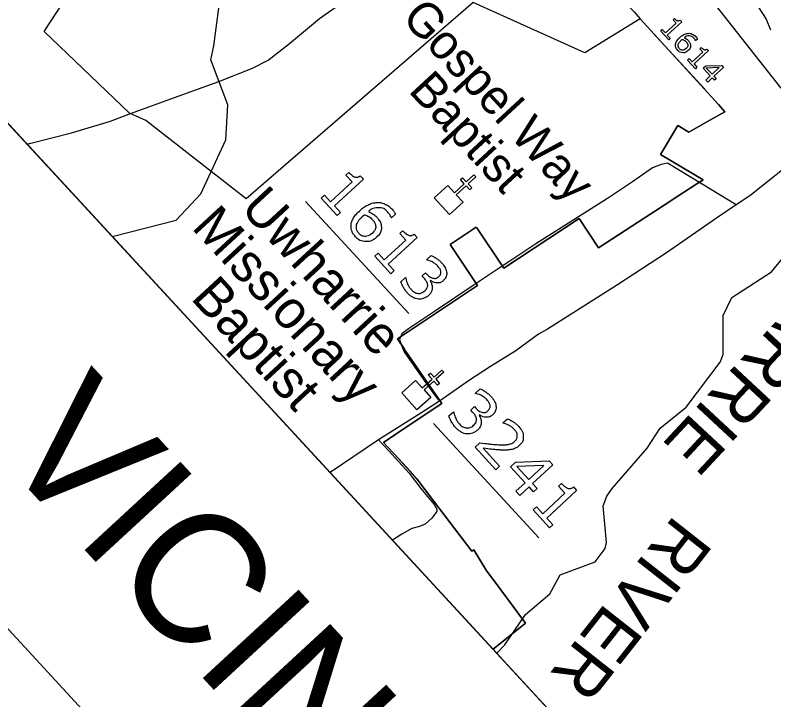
# Model space of a CAD drawing. Extents: x 1695041 to 1706254, y 786537 to 798223.
# Drawn here: x 1702759.1 to 1702961, y 796754.5 to 796936.6 of the extents above; entities that cross this region are included whole.
import ezdxf

# ---------------------------------------------------------------- set-up
doc = ezdxf.new("R2010")
doc.units = 0
for name, color, linetype in [('Default', 7, 'Continuous'), ('Old_Level_2', 7, 'Continuous'), ('Old_Level_30', 7, 'Continuous'), ('Old_Level_32', 7, 'Continuous')]:
    doc.layers.add(name, color=color, linetype=linetype)

msp = doc.modelspace()

# ---------------------------------------------------------------- linework, layer by layer
at = {"layer": 'Default'}
for p, q in [((1702636.99, 797037.98), (1703265.12, 796357.5)), ((1702683.46, 796987.65), (1702886.28, 796767.92)), ((1702683.46, 796987.65), (1702886.28, 796767.92)), ((1702569.98, 796976.12), (1703198.1, 796295.64)), ((1702928.77, 796931.9), (1702942.59, 796916.93)), ((1702836.31, 796887.01), (1702863.82, 796857.2)), ((1702870.38, 796828.01), (1702898.46, 796797.59)), ((1702859.9, 796819.89), (1702865.99, 796813.24)), ((1702859.9, 796819.89), (1702865.99, 796813.24)), ((1702886.28, 796767.92), (1702888.97, 796765))]:
    msp.add_line(p, q, dxfattribs=at)
for points in [[(1703207.65, 797564.73), (1702636.99, 797037.98), (1703265.12, 796357.5), (1703835.77, 796884.26)], [(1702925.41, 796935.68), (1702910.71, 796926.62), (1702880.93, 796939.99), (1702820.56, 796887.72), (1702793.87, 796908.61), (1702789.51, 796910.51), (1702766.84, 796932.24), (1702771.83, 796939.94), (1702770.51, 796956.02), (1702774.36, 796959.43), (1702767.63, 796967.11), (1702772.81, 796971.72), (1702783.62, 796979.72), (1702783.43, 796981.21), (1702797.1, 796993.15), (1702779.26, 797011.19), (1702762.34, 797007.42), (1702760.1, 797010.1), (1702716.96, 796974.07), (1702714.33, 796993.89), (1702694.56, 796987.03), (1702684.89, 796991.85), (1702683.46, 796987.65)], [(1702925.41, 796935.68), (1702910.71, 796926.62), (1702880.93, 796939.99), (1702820.56, 796887.72), (1702793.87, 796908.61), (1702789.51, 796910.51), (1702766.84, 796932.24), (1702771.83, 796939.94), (1702770.51, 796956.02), (1702774.36, 796959.43), (1702767.63, 796967.11), (1702772.81, 796971.72), (1702783.62, 796979.72), (1702783.43, 796981.21), (1702797.1, 796993.15), (1702779.26, 797011.19), (1702762.34, 797007.42), (1702760.1, 797010.1), (1702716.96, 796974.07), (1702714.33, 796993.89), (1702694.56, 796987.03), (1702684.89, 796991.85), (1702683.46, 796987.65)], [(1702969.78, 796940.73), (1702969.33, 796939.28), (1702965.99, 796925.42), (1702964.15, 796917.75), (1702962.89, 796917.17), (1702932.55, 796955.73), (1702924.73, 796965.57), (1702922.88, 796967.64), (1702932.74, 796975.84), (1702936, 796978.21), (1702924.89, 796991.85), (1702917.84, 796986.09), (1702911.88, 796981.22), (1702914.79, 796977.7), (1702908.54, 796972.43), (1702903.8, 796968.42), (1702898.61, 796964.04), (1702901.91, 796960.89), (1702912.63, 796949.21), (1702923.77, 796937.5), (1702925.41, 796935.68)], [(1702969.78, 796940.73), (1702969.33, 796939.28), (1702965.99, 796925.42), (1702964.15, 796917.75), (1702962.89, 796917.17), (1702932.55, 796955.73), (1702924.73, 796965.57), (1702922.88, 796967.64), (1702932.74, 796975.84), (1702936, 796978.21), (1702924.89, 796991.85), (1702917.84, 796986.09), (1702911.88, 796981.22), (1702914.79, 796977.7), (1702908.54, 796972.43), (1702903.8, 796968.42), (1702898.61, 796964.04), (1702901.91, 796960.89), (1702912.63, 796949.21), (1702923.77, 796937.5), (1702925.41, 796935.68)], [(1702929.65, 796971.07), (1702932.14, 796967.77), (1702939.12, 796959.62), (1702945.77, 796951.98), (1702950, 796947.1), (1702951.94, 796944.71), (1702954.16, 796942.3), (1702956.83, 796938.82), (1702958.88, 796935.58), (1702960.04, 796932.69)], [(1702811.13, 796924.7), (1702811.93, 796928.47), (1702813.39, 796939.15), (1702814.28, 796944.71)], [(1702930.77, 796899.57), (1702935.39, 796907.26), (1702938.35, 796905.48), (1702945.38, 796909.47), (1702945.54, 796909.57), (1702947.96, 796910.93), (1702946.25, 796912.81), (1702925.41, 796935.68)], [(1702930.77, 796899.57), (1702935.39, 796907.26), (1702938.35, 796905.48), (1702945.38, 796909.47), (1702945.54, 796909.57), (1702947.96, 796910.93), (1702946.25, 796912.81), (1702925.41, 796935.68)], [(1702925.41, 796935.68), (1702946.25, 796912.81), (1702947.96, 796910.93), (1702945.54, 796909.57), (1702945.38, 796909.47), (1702938.35, 796905.48), (1702935.39, 796907.26), (1702930.77, 796899.57)], [(1702925.41, 796935.68), (1702946.25, 796912.81), (1702947.96, 796910.93), (1702945.54, 796909.57), (1702945.38, 796909.47), (1702938.35, 796905.48), (1702935.39, 796907.26), (1702930.77, 796899.57)], [(1702932.98, 796930.06), (1702930.86, 796932.36), (1702931.29, 796932.76), (1702932.11, 796931.88), (1702934.95, 796934.5), (1702934.14, 796935.39), (1702934.53, 796935.74)], [(1702936.03, 796935.3), (1702936.44, 796934.86), (1702932.62, 796931.33), (1702933.41, 796930.46), (1702932.98, 796930.06)], [(1702940.69, 796930.26), (1702940.14, 796929.75), (1702940.12, 796929.78)], [(1702940.08, 796922.37), (1702937.96, 796924.67), (1702938.39, 796925.07), (1702939.21, 796924.19), (1702942.05, 796926.81), (1702941.24, 796927.69), (1702941.63, 796928.05)], [(1702943.13, 796927.61), (1702943.54, 796927.17), (1702939.72, 796923.64), (1702940.51, 796922.77), (1702940.08, 796922.37)], [(1702784.91, 796877.73), (1702801.89, 796882.09), (1702808.46, 796889.09), (1702815.17, 796903.46), (1702815.67, 796912.73), (1702811.13, 796924.7)], [(1702945.14, 796919.29), (1702944.56, 796919.92), (1702943.36, 796918.82), (1702942.86, 796919.36), (1702944.05, 796920.47), (1702942.18, 796922.5), (1702942.83, 796923.11), (1702947.12, 796923.26), (1702947.61, 796922.73), (1702945.02, 796920.34), (1702945.6, 796919.71), (1702945.14, 796919.29)], [(1702944.51, 796920.89), (1702946.43, 796922.66), (1702942.99, 796922.54), (1702944.51, 796920.89)], [(1702942.05, 796892.68), (1702942.19, 796892.77), (1702930.77, 796899.57)], [(1702942.05, 796892.68), (1702942.19, 796892.77), (1702930.77, 796899.57)], [(1702930.77, 796899.57), (1702942.19, 796892.77), (1702942.05, 796892.68)], [(1702930.77, 796899.57), (1702942.19, 796892.77), (1702942.05, 796892.68)], [(1702844.78, 796883.32), (1702840.52, 796887.94), (1702841.39, 796888.74), (1702843.03, 796886.97), (1702848.75, 796892.25), (1702847.11, 796894.03), (1702847.89, 796894.75)], [(1702850.92, 796893.86), (1702851.74, 796892.97), (1702844.05, 796885.86), (1702845.66, 796884.12), (1702844.78, 796883.32)], [(1702859.9, 796819.89), (1702858.28, 796821.64), (1702857.11, 796822.95), (1702864.45, 796827.87), (1702872.64, 796833.28), (1702862.9, 796847.39), (1702862.66, 796847.75), (1702860.8, 796850.5), (1702882.15, 796864.71), (1702874.8, 796875.62), (1702881.78, 796880.22), (1702881.96, 796880), (1702889.15, 796869.31), (1702909.2, 796882.51), (1702914.34, 796874.72), (1702933.54, 796887.23), (1702933.66, 796887.31), (1702940.51, 796891.73), (1702942.05, 796892.68)], [(1702859.9, 796819.89), (1702858.28, 796821.64), (1702857.11, 796822.95), (1702864.45, 796827.87), (1702872.64, 796833.28), (1702862.9, 796847.39), (1702862.66, 796847.75), (1702860.8, 796850.5), (1702882.15, 796864.71), (1702874.8, 796875.62), (1702881.78, 796880.22), (1702881.96, 796880), (1702889.15, 796869.31), (1702909.2, 796882.51), (1702914.34, 796874.72), (1702933.54, 796887.23), (1702933.66, 796887.31), (1702940.51, 796891.73), (1702942.05, 796892.68)], [(1702942.05, 796892.68), (1702940.51, 796891.73), (1702933.66, 796887.31), (1702933.54, 796887.23), (1702914.34, 796874.72), (1702909.2, 796882.51), (1702889.15, 796869.31), (1702881.96, 796880), (1702881.78, 796880.22), (1702874.8, 796875.62), (1702882.15, 796864.71), (1702860.8, 796850.5), (1702862.66, 796847.75), (1702862.9, 796847.39), (1702872.64, 796833.28), (1702864.45, 796827.87), (1702857.11, 796822.95), (1702858.28, 796821.64), (1702859.9, 796819.89)], [(1702942.05, 796892.68), (1702940.51, 796891.73), (1702933.66, 796887.31), (1702933.54, 796887.23), (1702914.34, 796874.72), (1702909.2, 796882.51), (1702889.15, 796869.31), (1702881.96, 796880), (1702881.78, 796880.22), (1702874.8, 796875.62), (1702882.15, 796864.71), (1702860.8, 796850.5), (1702862.66, 796847.75), (1702862.9, 796847.39), (1702872.64, 796833.28), (1702864.45, 796827.87), (1702857.11, 796822.95), (1702858.28, 796821.64), (1702859.9, 796819.89)], [(1702860.3, 796883.7), (1702859.2, 796882.68), (1702859.15, 796882.74)], [(1702859.08, 796867.83), (1702854.81, 796872.46), (1702855.68, 796873.26), (1702857.32, 796871.48), (1702863.05, 796876.77), (1702861.41, 796878.54), (1702862.19, 796879.27)], [(1702865.22, 796878.38), (1702866.04, 796877.49), (1702858.34, 796870.38), (1702859.95, 796868.64), (1702859.08, 796867.83)], [(1702868.63, 796871.5), (1702868.58, 796871.56), (1702869.77, 796872.67)], [(1702861.72, 796865.68), (1702862.92, 796866.79), (1702863, 796866.7)], [(1702867.83, 796866.71), (1702867.35, 796867.22), (1702868.3, 796868.1), (1702868.67, 796867.7)], [(1702869.59, 796865.98), (1702869.51, 796865.9)], [(1702881.62, 796835.98), (1702881.57, 796836.04), (1702882.81, 796837.19)], [(1702880.79, 796831.03), (1702880.3, 796831.56), (1702881.28, 796832.47), (1702881.66, 796832.05)], [(1702874.49, 796829.97), (1702875.72, 796831.11), (1702875.81, 796831.03)], [(1702882.61, 796830.28), (1702882.53, 796830.2)], [(1702888.94, 796828.06), (1702888.88, 796828.12), (1702890.13, 796829.26)], [(1702886.99, 796815.69), (1702881.47, 796821.67), (1702882.71, 796822.82)], [(1702865.99, 796813.24), (1702864.25, 796815.22), (1702859.9, 796819.89)], [(1702865.99, 796813.24), (1702864.25, 796815.22), (1702859.9, 796819.89)], [(1702883.62, 796821.39), (1702888.01, 796816.63), (1702886.99, 796815.69)], [(1702897.04, 796809.78), (1702895.83, 796811.1), (1702893.34, 796808.8), (1702892.29, 796809.94), (1702894.78, 796812.23), (1702890.88, 796816.46), (1702892.24, 796817.72), (1702901.16, 796818.04), (1702902.17, 796816.95), (1702896.78, 796811.97), (1702897.99, 796810.66), (1702897.04, 796809.78)], [(1702895.73, 796813.11), (1702899.72, 796816.79), (1702892.57, 796816.54), (1702895.73, 796813.11)], [(1702886.28, 796767.92), (1702894.9, 796774.87), (1702888.3, 796783.71), (1702884.4, 796788.94), (1702881.13, 796794.32), (1702880.63, 796794), (1702870.44, 796807.4), (1702865.99, 796813.24)], [(1702886.28, 796767.92), (1702894.9, 796774.87), (1702888.3, 796783.71), (1702884.4, 796788.94), (1702881.13, 796794.32), (1702880.63, 796794), (1702870.44, 796807.4), (1702865.99, 796813.24)], [(1702865.99, 796813.24), (1702870.44, 796807.4), (1702880.63, 796794), (1702881.13, 796794.32), (1702884.4, 796788.94), (1702888.3, 796783.71), (1702894.9, 796774.87), (1702886.28, 796767.92)], [(1702865.99, 796813.24), (1702870.44, 796807.4), (1702880.63, 796794), (1702881.13, 796794.32), (1702884.4, 796788.94), (1702888.3, 796783.71), (1702894.9, 796774.87), (1702886.28, 796767.92)], [(1702901.29, 796800.2), (1702896.88, 796804.97), (1702897.78, 796805.81), (1702899.47, 796803.97), (1702905.39, 796809.43), (1702903.69, 796811.27), (1702904.5, 796812.01)], [(1702907.63, 796811.09), (1702908.48, 796810.17), (1702900.52, 796802.83), (1702902.19, 796801.03), (1702901.29, 796800.2)]]:
    msp.add_lwpolyline(points, dxfattribs=at)
for points in [[(1702874.18, 796891.31), (1702875.97, 796889.38), (1702878.56, 796891.77), (1702877.55, 796892.85), (1702878.1, 796893.35), (1702879.1, 796892.27), (1702881.14, 796894.15), (1702881.64, 796893.61), (1702879.6, 796891.72), (1702880.6, 796890.64), (1702880.06, 796890.14), (1702879.06, 796891.22), (1702876.47, 796888.84), (1702878.28, 796886.87), (1702874.66, 796883.54), (1702870.57, 796887.97)], [(1702865.63, 796839.42), (1702867.39, 796837.47), (1702870.01, 796839.81), (1702869.02, 796840.91), (1702869.57, 796841.41), (1702870.56, 796840.31), (1702872.63, 796842.16), (1702873.12, 796841.61), (1702871.05, 796839.76), (1702872.04, 796838.66), (1702871.49, 796838.16), (1702870.5, 796839.26), (1702867.89, 796836.91), (1702869.66, 796834.93), (1702866, 796831.64), (1702861.97, 796836.13)]]:
    msp.add_lwpolyline(points, close=True, dxfattribs=at)
for points in [[(1702934.53, 796935.74), (1702934.69, 796935.56), (1702934.91, 796935.39), (1702935.13, 796935.21), (1702935.29, 796935.16), (1702935.48, 796935.09), (1702935.66, 796935.12), (1702935.84, 796935.14), (1702936.03, 796935.3)], [(1702938.19, 796927.18), (1702937.54, 796926.59), (1702936.74, 796926.63), (1702935.94, 796926.68), (1702935.37, 796927.3), (1702935.08, 796927.61), (1702934.94, 796927.96), (1702934.8, 796928.31), (1702934.81, 796928.68), (1702934.82, 796929.14), (1702935.08, 796929.64), (1702935.35, 796930.13), (1702935.9, 796930.64), (1702936.47, 796931.16), (1702937.02, 796931.44), (1702937.56, 796931.72), (1702938.15, 796931.77), (1702938.7, 796931.81), (1702939.25, 796931.59), (1702939.8, 796931.36), (1702940.28, 796930.83), (1702940.44, 796930.66), (1702940.53, 796930.53), (1702940.62, 796930.41), (1702940.69, 796930.26)], [(1702940.12, 796929.78), (1702940.09, 796929.9), (1702939.98, 796930.1), (1702939.87, 796930.29), (1702939.71, 796930.46), (1702939.15, 796931.07), (1702938.43, 796931.08), (1702937.71, 796931.09), (1702937, 796930.55), (1702937.37, 796930.45), (1702937.66, 796930.28), (1702937.95, 796930.12), (1702938.23, 796929.82), (1702938.48, 796929.55), (1702938.62, 796929.29), (1702938.76, 796929.04), (1702938.81, 796928.69), (1702938.86, 796928.28), (1702938.72, 796927.9), (1702938.57, 796927.53), (1702938.19, 796927.18)], [(1702937.63, 796927.74), (1702937.89, 796927.98), (1702938, 796928.22), (1702938.1, 796928.46), (1702938.06, 796928.76), (1702938.03, 796928.97), (1702937.91, 796929.16), (1702937.79, 796929.34), (1702937.63, 796929.52), (1702937.41, 796929.76), (1702937.16, 796929.91), (1702936.91, 796930.07), (1702936.59, 796930.18), (1702936.52, 796930.12), (1702936.46, 796930.07), (1702936.4, 796930.02), (1702936.31, 796929.94), (1702935.86, 796929.53), (1702935.69, 796929.19), (1702935.51, 796928.86), (1702935.51, 796928.56), (1702935.51, 796928.31), (1702935.59, 796928.11), (1702935.67, 796927.9), (1702935.84, 796927.72), (1702936.22, 796927.31), (1702936.69, 796927.31), (1702937.16, 796927.3), (1702937.63, 796927.74)], [(1702941.63, 796928.05), (1702941.79, 796927.87), (1702942.01, 796927.69), (1702942.23, 796927.52), (1702942.39, 796927.46), (1702942.58, 796927.4), (1702942.76, 796927.42), (1702942.94, 796927.45), (1702943.13, 796927.61)], [(1702847.89, 796894.75), (1702848.23, 796894.39), (1702848.67, 796894.03), (1702849.11, 796893.67), (1702849.42, 796893.57), (1702849.81, 796893.44), (1702850.17, 796893.49), (1702850.53, 796893.54), (1702850.92, 796893.86)], [(1702855.26, 796877.52), (1702853.96, 796876.31), (1702852.35, 796876.41), (1702850.73, 796876.51), (1702849.58, 796877.75), (1702849, 796878.38), (1702848.72, 796879.08), (1702848.44, 796879.78), (1702848.46, 796880.53), (1702848.48, 796881.46), (1702849.02, 796882.45), (1702849.56, 796883.45), (1702850.67, 796884.47), (1702851.8, 796885.52), (1702852.91, 796886.08), (1702854.01, 796886.65), (1702855.18, 796886.75), (1702856.3, 796886.84), (1702857.4, 796886.38), (1702858.5, 796885.92), (1702859.48, 796884.86), (1702859.79, 796884.52), (1702859.98, 796884.26), (1702860.16, 796884.01), (1702860.3, 796883.7)], [(1702859.15, 796882.74), (1702859.09, 796882.98), (1702858.87, 796883.38), (1702858.64, 796883.78), (1702858.33, 796884.11), (1702857.2, 796885.35), (1702855.75, 796885.37), (1702854.3, 796885.39), (1702852.87, 796884.3), (1702853.61, 796884.09), (1702854.19, 796883.76), (1702854.78, 796883.43), (1702855.34, 796882.82), (1702855.84, 796882.27), (1702856.13, 796881.77), (1702856.41, 796881.26), (1702856.51, 796880.54), (1702856.62, 796879.71), (1702856.33, 796878.97), (1702856.03, 796878.22), (1702855.26, 796877.52)], [(1702854.14, 796878.63), (1702854.67, 796879.13), (1702854.88, 796879.61), (1702855.08, 796880.09), (1702855, 796880.68), (1702854.94, 796881.12), (1702854.71, 796881.49), (1702854.47, 796881.86), (1702854.14, 796882.21), (1702853.7, 796882.7), (1702853.2, 796883.01), (1702852.69, 796883.32), (1702852.05, 796883.54), (1702851.91, 796883.44), (1702851.79, 796883.34), (1702851.66, 796883.23), (1702851.49, 796883.07), (1702850.58, 796882.23), (1702850.23, 796881.56), (1702849.88, 796880.89), (1702849.88, 796880.29), (1702849.87, 796879.79), (1702850.03, 796879.38), (1702850.2, 796878.96), (1702850.53, 796878.6), (1702851.3, 796877.77), (1702852.24, 796877.76), (1702853.19, 796877.76), (1702854.14, 796878.63)], [(1702862.19, 796879.27), (1702862.52, 796878.9), (1702862.96, 796878.55), (1702863.4, 796878.19), (1702863.71, 796878.08), (1702864.1, 796877.95), (1702864.46, 796878), (1702864.82, 796878.06), (1702865.22, 796878.38)], [(1702869.77, 796872.67), (1702870.35, 796872.44), (1702871.15, 796871.92), (1702871.95, 796871.39), (1702872.53, 796870.76), (1702873.11, 796870.13), (1702873.44, 796869.55), (1702873.76, 796868.97), (1702873.86, 796868.35), (1702873.97, 796867.68), (1702873.78, 796867.11), (1702873.58, 796866.53), (1702873.06, 796866.05), (1702872.35, 796865.39), (1702871.35, 796865.41), (1702870.36, 796865.42), (1702869.59, 796865.98)], [(1702868.67, 796867.7), (1702869.47, 796866.82), (1702870.32, 796866.64), (1702871.16, 796866.46), (1702871.87, 796867.11), (1702872.18, 796867.39), (1702872.29, 796867.74), (1702872.4, 796868.09), (1702872.33, 796868.46), (1702872.25, 796868.85), (1702872.05, 796869.18), (1702871.85, 796869.51), (1702871.52, 796869.87), (1702871.01, 796870.42), (1702870.25, 796870.85), (1702869.49, 796871.29), (1702868.63, 796871.5)], [(1702863, 796866.7), (1702863.13, 796865.92), (1702863.52, 796865.06), (1702863.92, 796864.21), (1702864.49, 796863.59), (1702864.82, 796863.23), (1702865.32, 796862.93), (1702865.82, 796862.64), (1702866.29, 796862.6), (1702866.78, 796862.57), (1702867.21, 796862.72), (1702867.63, 796862.88), (1702868.1, 796863.31), (1702868.56, 796863.73), (1702868.73, 796864.16), (1702868.89, 796864.58), (1702868.83, 796865), (1702868.77, 796865.42), (1702868.49, 796865.85), (1702868.22, 796866.28), (1702867.83, 796866.71)], [(1702870.09, 796864.16), (1702870.1, 796863.65), (1702869.89, 796863.13), (1702869.68, 796862.61), (1702869.09, 796862.06), (1702868.5, 796861.52), (1702867.82, 796861.28), (1702867.13, 796861.04), (1702866.42, 796861.09), (1702865.62, 796861.15), (1702864.89, 796861.56), (1702864.16, 796861.96), (1702863.52, 796862.66), (1702862.86, 796863.37), (1702862.39, 796864.21), (1702861.93, 796865.06), (1702861.72, 796865.68)], [(1702869.51, 796865.9), (1702869.72, 796865.59), (1702869.9, 796865.1), (1702870.08, 796864.6), (1702870.09, 796864.16)], [(1702881.66, 796832.05), (1702882.5, 796831.15), (1702883.37, 796830.96), (1702884.24, 796830.77), (1702884.97, 796831.44), (1702885.29, 796831.74), (1702885.4, 796832.1), (1702885.52, 796832.45), (1702885.45, 796832.84), (1702885.37, 796833.24), (1702885.16, 796833.58), (1702884.95, 796833.93), (1702884.61, 796834.3), (1702884.09, 796834.86), (1702883.3, 796835.31), (1702882.51, 796835.76), (1702881.62, 796835.98)], [(1702882.81, 796837.19), (1702883.4, 796836.96), (1702884.23, 796836.41), (1702885.05, 796835.87), (1702885.66, 796835.21), (1702886.25, 796834.57), (1702886.59, 796833.96), (1702886.93, 796833.36), (1702887.03, 796832.72), (1702887.14, 796832.03), (1702886.94, 796831.44), (1702886.74, 796830.85), (1702886.2, 796830.35), (1702885.47, 796829.67), (1702884.44, 796829.69), (1702883.41, 796829.7), (1702882.61, 796830.28)], [(1702883.13, 796828.39), (1702883.14, 796827.87), (1702882.92, 796827.33), (1702882.71, 796826.79), (1702882.1, 796826.23), (1702881.49, 796825.67), (1702880.78, 796825.43), (1702880.08, 796825.18), (1702879.34, 796825.23), (1702878.51, 796825.29), (1702877.76, 796825.71), (1702877, 796826.13), (1702876.34, 796826.85), (1702875.66, 796827.58), (1702875.18, 796828.45), (1702874.7, 796829.33), (1702874.49, 796829.97)], [(1702875.81, 796831.03), (1702875.94, 796830.22), (1702876.35, 796829.33), (1702876.76, 796828.45), (1702877.35, 796827.81), (1702877.69, 796827.44), (1702878.2, 796827.13), (1702878.72, 796826.82), (1702879.2, 796826.79), (1702879.72, 796826.76), (1702880.16, 796826.91), (1702880.59, 796827.07), (1702881.07, 796827.52), (1702881.55, 796827.95), (1702881.72, 796828.39), (1702881.89, 796828.83), (1702881.83, 796829.27), (1702881.76, 796829.7), (1702881.48, 796830.15), (1702881.2, 796830.59), (1702880.79, 796831.03)], [(1702882.53, 796830.2), (1702882.75, 796829.87), (1702882.93, 796829.36), (1702883.12, 796828.86), (1702883.13, 796828.39)], [(1702882.71, 796822.82), (1702883.82, 796822.69), (1702884.94, 796822.56), (1702886.05, 796822.42), (1702887.07, 796822.37), (1702889.23, 796822.24), (1702890.27, 796822.42), (1702891.3, 796822.6), (1702892.06, 796823.29), (1702892.74, 796823.93), (1702892.71, 796824.74), (1702892.68, 796825.55), (1702891.93, 796826.37), (1702891.43, 796826.91), (1702890.66, 796827.36), (1702889.89, 796827.82), (1702888.94, 796828.06)], [(1702890.13, 796829.26), (1702890.72, 796829.03), (1702891.54, 796828.49), (1702892.37, 796827.94), (1702892.97, 796827.29), (1702894.23, 796825.93), (1702894.29, 796824.55), (1702894.34, 796823.18), (1702893.22, 796822.14), (1702892.72, 796821.68), (1702892.17, 796821.4), (1702891.61, 796821.13), (1702890.99, 796821.02), (1702890.41, 796820.91), (1702889.77, 796820.89), (1702889.13, 796820.88), (1702888.28, 796820.92), (1702887.08, 796820.98), (1702885.87, 796821.12), (1702884.66, 796821.26), (1702883.62, 796821.39)], [(1702904.5, 796812.01), (1702904.84, 796811.64), (1702905.3, 796811.27), (1702905.76, 796810.9), (1702906.08, 796810.79), (1702906.48, 796810.65), (1702906.85, 796810.71), (1702907.22, 796810.76), (1702907.63, 796811.09)]]:
    msp.add_open_spline(points, degree=3, dxfattribs=at)
at = {"layer": 'Old_Level_30'}
msp.add_lwpolyline([(1702887.23, 796766.89), (1702889.39, 796769.09), (1702894.9, 796777.12), (1702901.35, 796782.68), (1702904.1, 796787.74), (1702913.4, 796791.17), (1702916.06, 796794.73), (1702916.48, 796796.29), (1702915.55, 796806.06), (1702916.52, 796808.61), (1702917.91, 796810.67), (1702927.3, 796821.38), (1702930.7, 796826.69), (1702937.63, 796832.29), (1702946.66, 796844.31), (1702947.45, 796846.31), (1702947.44, 796856.73), (1702949.77, 796861.52), (1702960.34, 796868.35), (1702963.22, 796871.79)], dxfattribs=at)
at = {"layer": 'Old_Level_32'}
for points in [[(1702789.79, 796910.41), (1702799.56, 796914.01), (1702813.28, 796918.99), (1702822.2, 796922.52), (1702826.4, 796924.64), (1702832.11, 796929.1), (1702840.04, 796935.72), (1702849.05, 796942.09), (1702861.71, 796950.19), (1702864.47, 796951.59), (1702869.27, 796953.44), (1702883.42, 796958.45), (1702894.89, 796961.85), (1702896.19, 796962.14), (1702898.39, 796962.2)], [(1702989.16, 796915.69), (1702982, 796910.38), (1702979.46, 796908.31), (1702964.12, 796896.16), (1702954.61, 796888.59), (1702950.95, 796886.16)], [(1702762.25, 796902.28), (1702763.26, 796902.53), (1702774.12, 796905.31), (1702784.49, 796908.38), (1702789.79, 796910.41)], [(1702941.91, 796891.64), (1702932.66, 796897.23), (1702930.96, 796896.88), (1702928.68, 796895.98), (1702923.33, 796892.26), (1702916.68, 796887.88), (1702897.62, 796875.75)], [(1702950.95, 796886.16), (1702941.91, 796891.64)], [(1702950.95, 796886.16), (1702945.73, 796882.6), (1702932.36, 796873.36), (1702919.36, 796864.88), (1702900.75, 796853.09), (1702898.37, 796851.71), (1702892.29, 796847.32), (1702885.59, 796843.15), (1702880, 796839.48), (1702872.01, 796833.93)], [(1702897.62, 796875.75), (1702890.68, 796871.16), (1702887.87, 796869.28)], [(1702887.87, 796869.28), (1702881, 796864.68)], [(1702881, 796864.68), (1702870.95, 796857.94), (1702863.73, 796853.17), (1702861.98, 796851.83), (1702861.36, 796850.31), (1702861.8, 796848.96), (1702862.63, 796847.03), (1702867.88, 796839.44), (1702870.94, 796835.24), (1702872.01, 796833.93)], [(1702872.01, 796833.93), (1702867.07, 796830.72), (1702855.77, 796823.61)], [(1702855.77, 796823.61), (1702842.9, 796814.91)], [(1702855.77, 796823.61), (1702858.47, 796820.83), (1702863.95, 796814.75), (1702867.05, 796810.65), (1702870.61, 796806.44), (1702871.26, 796805.21), (1702871.27, 796804.55), (1702869.97, 796802.75)], [(1702869.97, 796802.75), (1702868.15, 796801.21), (1702866.72, 796800.56), (1702864.66, 796800.01), (1702861.99, 796798.5), (1702859.5, 796796.93)]]:
    msp.add_lwpolyline(points, dxfattribs=at)

# ---------------------------------------------------------------- texts
at = {"layer": 'Default'}
for s, height, rotation, p in [('Gospel Way', 9.224, 312.7091, (1702861.66, 796935.69)), ('Baptist', 9.224, 312.7091, (1702863.49, 796916.38)), ('Uwharrie', 10.146, 312.7091, (1702818.73, 796885.03)), ('UWHARRIE', 13.34, 227.0624, (1702997.3, 796893.62)), ('Missionary', 10.146, 312.7091, (1702805.78, 796880.01)), ('Baptist', 10.146, 312.7091, (1702805.55, 796861.21)), ('RIVER', 13.34, 231.8248, (1702934.66, 796803.97))]:
    msp.add_text(s, height=height, rotation=rotation, dxfattribs=at).set_placement(p)
at = {"layer": 'Old_Level_2'}
msp.add_text('VICINITY MAP', height=34.65, rotation=312.7091, dxfattribs=at).set_placement((1702753.74, 796820.15))

doc.saveas('drawing.dxf')
